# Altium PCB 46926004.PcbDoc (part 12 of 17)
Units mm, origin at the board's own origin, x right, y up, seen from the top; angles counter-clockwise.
Board outline 250 x 200 mm, 6 copper layers (Top Layer, INT1_GND, INT2_SIG, INT3_SIG, INT4_GND, Bottom Layer), stack 1.71 mm thick; 1450 components, 1293 nets, 5656 pads, 2307 vias.
Unrouted connection lines stored in the file: 2.
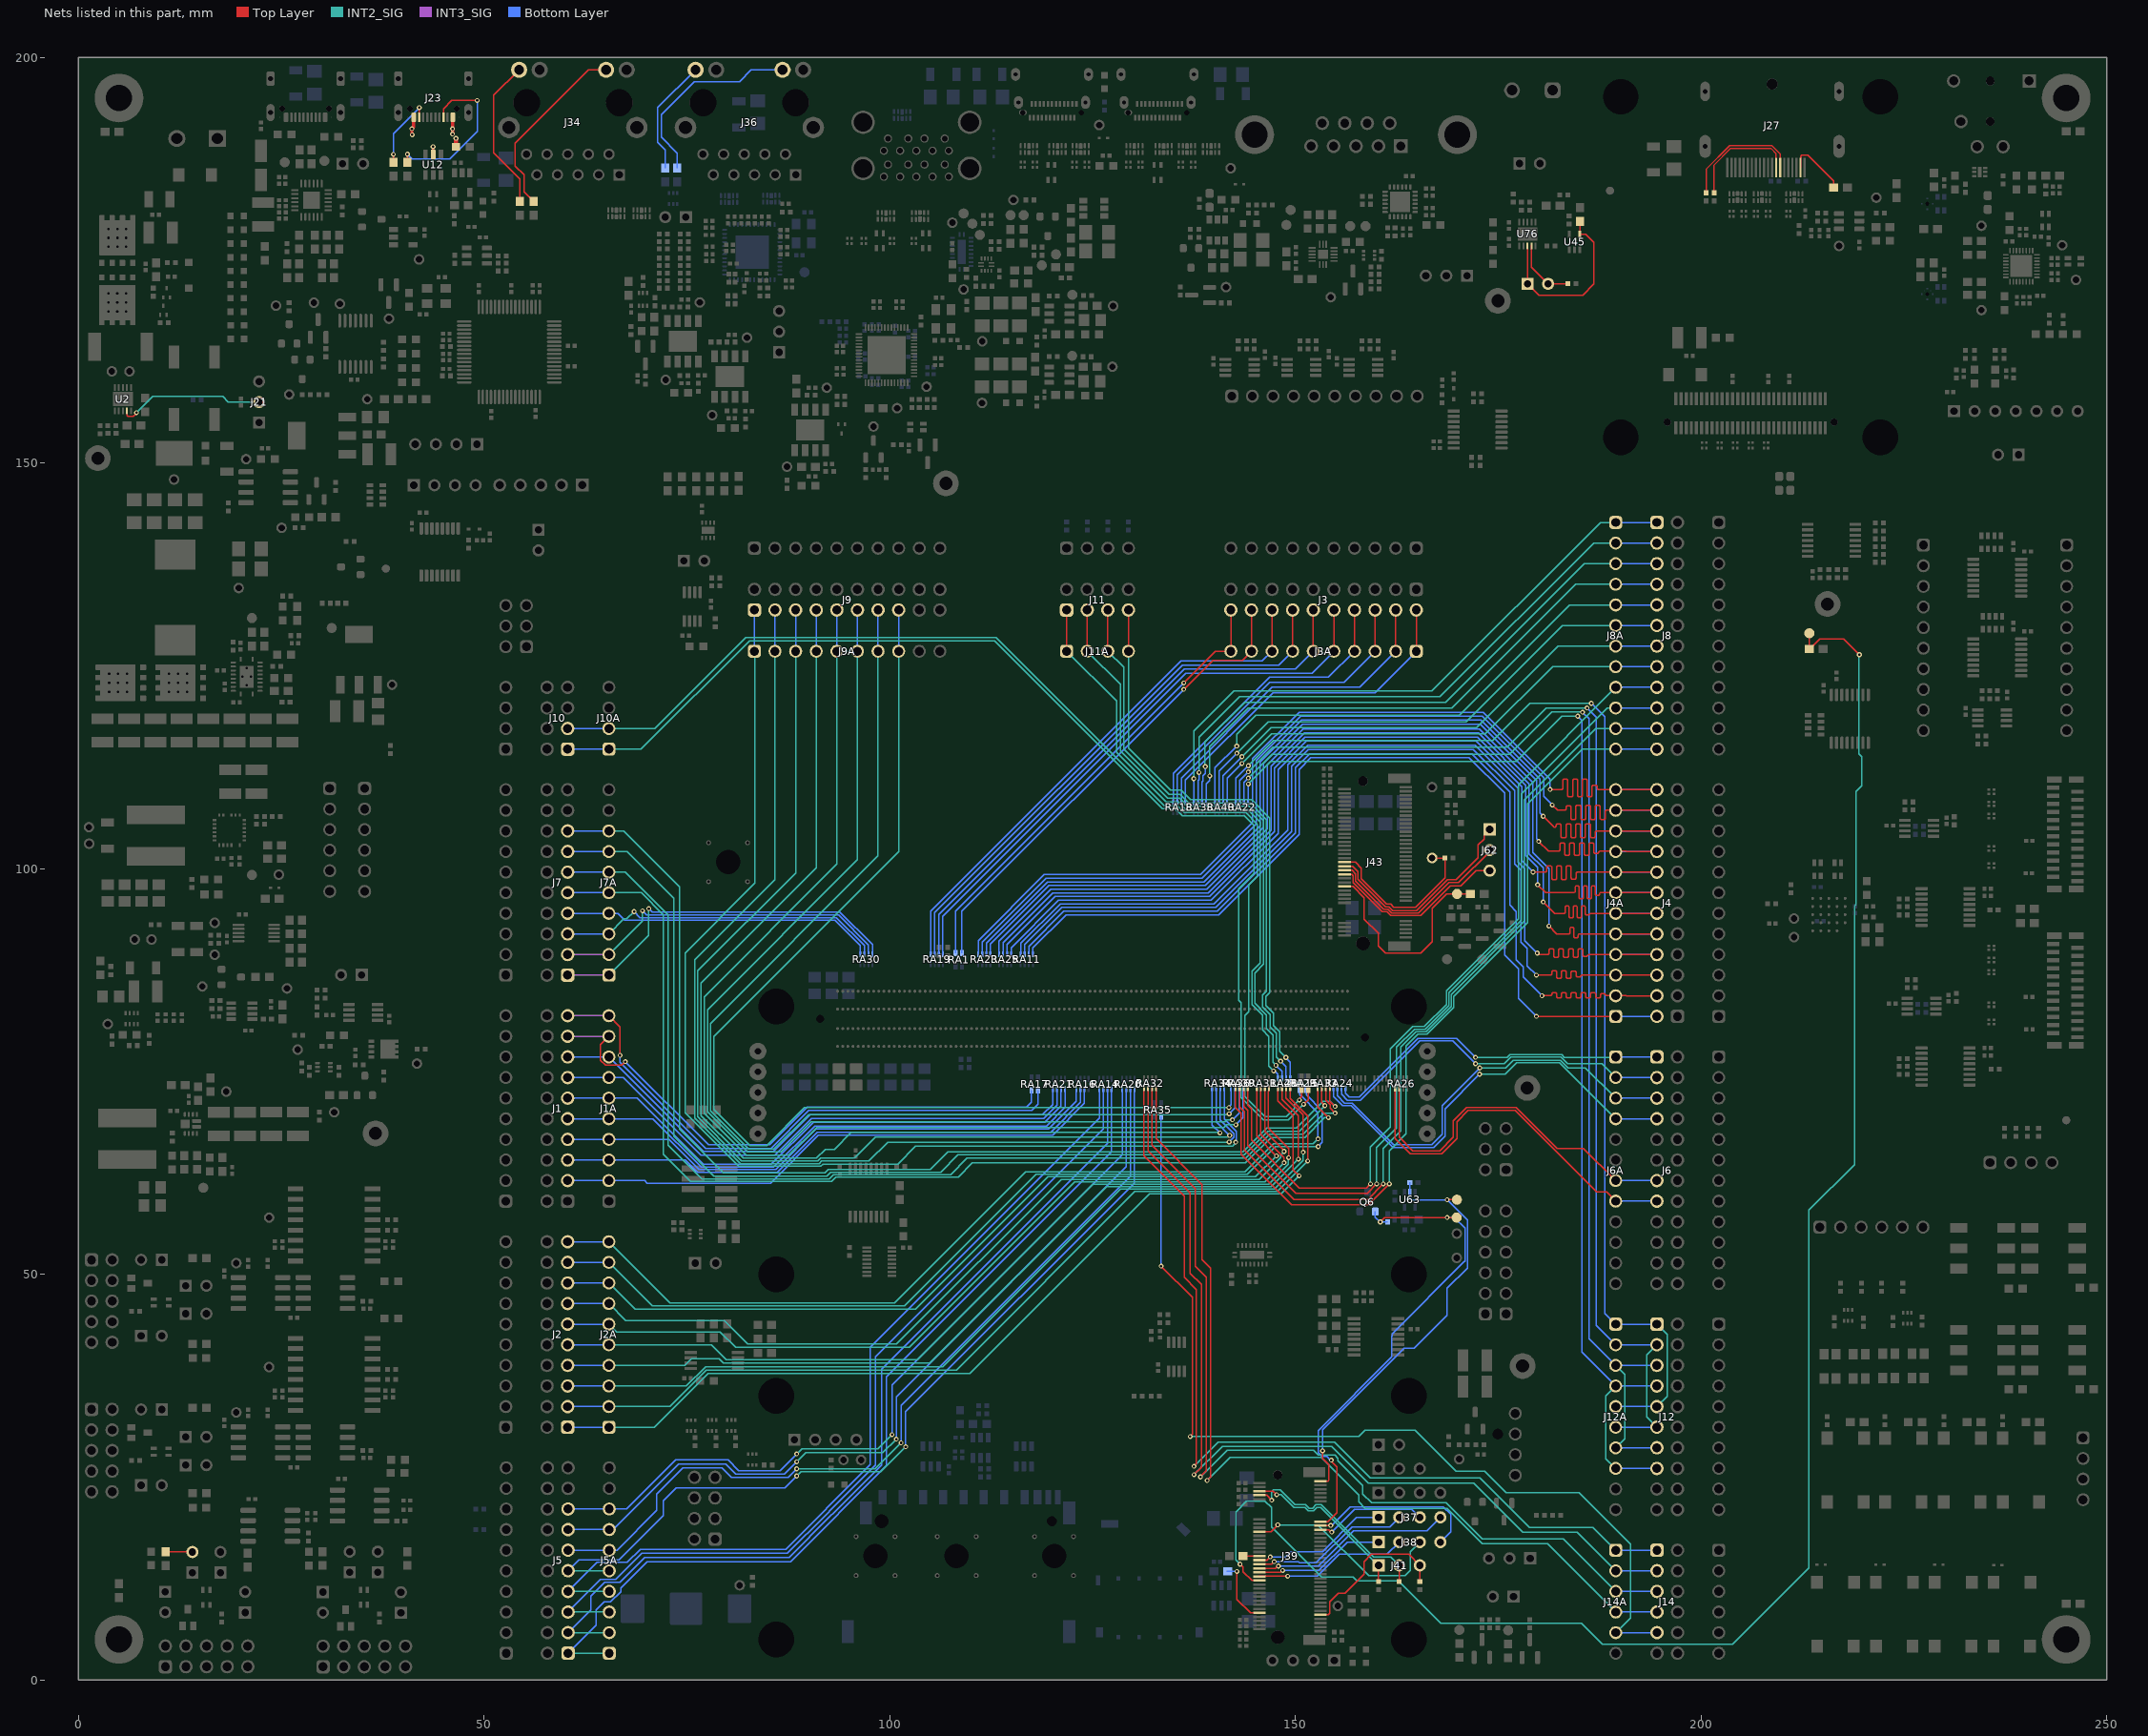
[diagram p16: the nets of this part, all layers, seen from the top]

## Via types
v1: diameter 0.6, hole 0.3, Top Layer to Bottom Layer, tented both sides, 2171 vias
v2: diameter 0.6, hole 0.3, Top Layer to Bottom Layer, 48 vias
v3: diameter 1, hole 0.5, Top Layer to Bottom Layer, tented both sides, 37 vias
v4: diameter 0.5, hole 0.2, Top Layer to Bottom Layer, tented both sides, 34 vias
v5: diameter 0.6, hole 0.3, Top Layer to Bottom Layer, tented bottom, 17 vias

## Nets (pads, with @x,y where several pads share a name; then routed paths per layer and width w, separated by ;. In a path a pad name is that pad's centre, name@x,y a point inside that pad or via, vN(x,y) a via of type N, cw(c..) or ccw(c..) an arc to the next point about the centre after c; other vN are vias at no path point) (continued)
NetJ1_3: J1.3 J1A.2 RA16.6 | length 69.7
  Bottom Layer w0.15: J1.3@60.3,61.56 69.78,61.56 70.09,61.25 85.285,61.25 91.214,67.179 120.106,67.179 123.996,71.069 RA16.6@123.996,72.872
NetJ1_5: J1.5 J1A.3 RA16.7 | length 69.1
  Bottom Layer w0.15: J1.5@60.3,64.1 J1A.3@65.38,64.1 74.8,64.1 76.316,62.584 86.117,62.584 91.067,67.534 119.836,67.534 123.496,71.194 RA16.7@123.496,72.872
NetJ1_7: J1.7 J1A.4 RA16.8 | length 69.3
  Bottom Layer w0.15: J1.7@60.3,66.64 J1A.4@65.38,66.64 72.817,66.64 76.523,62.934 85.952,62.934 90.916,67.899 119.567,67.899 122.996,71.328 RA16.8@122.996,72.872
NetJ1_9: J1.9 J1A.5 RA21.5 | length 69.1
  Bottom Layer w0.15: J1.9@60.3,69.18 64.05,69.18 J1A.5@65.38,69.18 70.82,69.18 76.766,63.234 85.692,63.234 90.752,68.295 119.302,68.295 121.61,70.602 RA21.5@121.61,72.87
NetJ1_11: J1.11 J1A.6 RA21.6 | length 69.3
  Bottom Layer w0.15: J1.11@60.3,71.72 64.05,71.72 J1A.6@65.38,71.72 68.885,71.72 77.056,63.549 85.397,63.549 90.574,68.725 119.119,68.725 121.11,70.716 RA21.6@121.11,72.87
NetJ1_13: J1.13 J1A.7 RA21.7 | length 68.9
  Bottom Layer w0.15: J1.13@60.3,74.26 J1A.7@65.38,74.26 67.14,74.26 76.717,64.683 85.87,64.683 90.38,69.193 118.957,69.193 120.61,70.846 RA21.7@120.61,72.87
NetJ1_15: J1.15 J1A.8 RA21.8 | length 68.9
  Bottom Layer w0.15: J1.15@60.3,76.8 J1A.8@65.3,76.8 ; J1A.8@65.38,76.8 77.037,65.143 85.678,65.143 90.189,69.654 118.831,69.654 120.11,70.934 RA21.8@120.11,72.87
NetJ1_17: J1.17 J1A.9 RA17.4 | length 69.9
  Top Layer w0.15: J1A.9@65.38,79.34 64.355,78.315 64.355,76.375 64.955,75.775 66.958,75.775 v1(67.4,76.217)
  INT3_SIG w0.15: J1.17@60.3,79.34 J1A.9@65.38,79.34
  Bottom Layer w0.15: v1(67.4,76.217) 77.664,65.953 85.195,65.953 89.842,70.6 116.856,70.6 117.476,71.22 RA17.4@117.476,72.67
NetJ1_19: J1.19 J1A.10 RA17.3 | length 71.2
  Top Layer w0.15: J1A.10@65.38,81.88 66.755,80.505 v1(66.755,77)
  INT3_SIG w0.15: J1.19@60.3,81.88 J1A.10@65.38,81.88
  Bottom Layer w0.15: v1(66.755,77) 66.755,76.119 77.334,65.54 85.347,65.54 90.007,70.2 117.482,70.2 118.276,70.993 RA17.3@118.276,72.67
NetJ2_1: J2.1 J2A.1 RA28.5 | length 114.9
  Top Layer w0.15: RA28.5@147.85,72.95 147.85,71.397 149.699,69.548 149.699,62.896 v1(150.444,62.152)
  INT2_SIG w0.15: J2A.1@65.38,31.16 70.96,31.16 77.6,37.8 109.9,37.8 132.017,59.917 148.209,59.917 v1(150.444,62.152)
  Bottom Layer w0.15: J2.1@60.3,31.16 J2A.1@65.38,31.16
NetJ2_3: J2.3 J2A.2 RA28.8 | length 113.6
  Top Layer w0.15: RA28.8@149.35,72.95 149.355,72.945 149.355,71.883 149.361,71.877 149.361,71.669 151.52,69.51 v1(151.52,63.97)
  INT2_SIG w0.15: J2A.2@65.38,33.7 72.893,33.7 77.407,38.214 108.214,38.214 130.217,60.217 147.766,60.217 v1(151.52,63.97)
  Bottom Layer w0.15: J2.3@60.3,33.7 J2A.2@65.38,33.7
NetJ2_5: J2.5 J2A.3 RA28.7 | length 111.9
  Top Layer w0.15: RA28.7@148.85,72.95 148.85,71.755 150.951,69.653 v1(150.951,65.052)
  INT2_SIG w0.15: J2A.3@65.38,36.24 74.94,36.24 77.3,38.6 106.5,38.6 128.417,60.517 147.418,60.517 150.951,64.05 v1(150.951,65.052)
  Bottom Layer w0.15: J2.5@60.3,36.24 J2A.3@65.38,36.24
NetJ2_7: J2.7 J2A.4 RA28.6 | length 110.6
  Top Layer w0.15: RA28.6@148.35,72.95 148.35,71.584 150.365,69.569 v1(150.365,64.207)
  INT2_SIG w0.15: J2A.4@65.38,38.78 74.751,38.78 75.576,39.605 78.969,39.605 79.524,39.05 104.95,39.05 126.717,60.817 146.975,60.817 v1(150.365,64.207)
  Bottom Layer w0.15: J2.7@60.3,38.78 J2A.4@65.38,38.78
NetJ2_9: J2.9 J2A.5 RA31.8 | length 110.1
  Top Layer w0.15: RA31.8@146.733,72.95 146.683,72.9 146.683,72.583 146.663,72.562 146.663,68.025 149.162,65.525 v1(149.162,64.369)
  INT2_SIG w0.15: J2A.5@65.28,41.32 J2A.5@65.38,41.32 78.004,41.32 79.824,39.5 103.4,39.5 125.017,61.117 146.704,61.117 149.14,63.553 149.14,64.347 v1(149.162,64.369)
  Bottom Layer w0.15: J2.9@60.3,41.32 J2A.5@65.38,41.32
NetJ2_11: J2.11 J2A.6 RA31.6 | length 109.3
  Top Layer w0.15: RA31.6@145.733,72.95 145.733,67.277 148.615,64.395 v1(148.615,63.771)
  INT2_SIG w0.15: J2A.6@65.38,43.86 66.355,42.885 79.109,42.885 80.994,41 102.4,41 122.817,61.417 146.261,61.417 v1(148.615,63.771)
  Bottom Layer w0.15: J2.11@60.3,43.86 J2A.6@65.38,43.86
NetJ2_13: J2.13 J2A.7 RA31.7 | length 109.2
  Top Layer w0.15: RA31.7@146.233,72.95 146.233,67.621 148.598,65.256 v1(148.598,65.155)
  INT2_SIG w0.15: J2A.7@65.38,46.4 67.48,44.3 79.6,44.3 82.5,41.4 100.824,41.4 121.141,61.717 145.527,61.717 148.193,64.383 148.193,64.711 148.598,65.117 v1(148.598,65.155)
  Bottom Layer w0.15: J2.13@60.3,46.4 J2A.7@65.38,46.4
NetJ2_15: J2.15 J2A.8 RA31.5 | length 105.9
  Top Layer w0.15: RA31.5@145.233,72.95 145.233,67.035 v1(147.668,64.6)
  INT2_SIG w0.15: J2A.8@65.38,48.94 68.62,45.7 103.2,45.7 119.517,62.017 145.085,62.017 v1(147.668,64.6)
  Bottom Layer w0.15: J2.15@60.3,48.94 J2A.8@65.38,48.94
NetJ2_17: J2.17 J2A.9 RA29.3 | length 110.9
  INT2_SIG w0.15: J2A.9@65.38,51.48 70.767,46.093 101.793,46.093 118.017,62.317 144.076,62.317 147.503,65.743 v1(152.801,65.743)
  Bottom Layer w0.15: J2.17@60.3,51.48 J2A.9@65.38,51.48 ; RA29.3@151.325,72.75 151.325,72.147 153.314,70.158 153.314,66.256 v1(152.801,65.743)
NetJ2_19: J2.19 J2A.10 RA29.4 | length 111
  INT2_SIG w0.15: J2A.10@65.38,54.02 72.9,46.5 100.6,46.5 116.717,62.617 143.8,62.617 147.283,66.1 152.193,66.1 v1(152.789,66.696)
  Bottom Layer w0.15: J2.19@60.3,54.02 J2A.10@65.38,54.02 ; RA29.4@150.525,72.75 150.557,72.718 150.557,72.125 150.675,72.007 150.695,72.007 152.789,69.913 v1(152.789,66.696)
NetJ3_2: J3.2 J3A.1 RA18.8 | length 42.8
  Top Layer w0.15: J3A.1@164.9,126.81 J3.2@164.9,131.89
  Bottom Layer w0.15: RA18.8@136.431,108.2 136.431,110.907 147.224,121.7 159.79,121.7 J3A.1@164.9,126.81
NetJ3_4: J3.4 J3A.2 RA18.7 | length 41
  Top Layer w0.15: J3A.2@162.36,126.81 J3.4@162.36,131.89
  Bottom Layer w0.15: RA18.7@135.931,108.2 135.931,111.182 147.148,122.4 157.95,122.4 J3A.2@162.36,126.81
NetJ3_6: J3.6 J3A.3 RA18.6 | length 39.2
  Top Layer w0.15: J3A.3@159.82,126.81 J3.6@159.82,131.89
  Bottom Layer w0.15: RA18.6@135.431,108.2 135.431,111.592 146.839,123 156.01,123 J3A.3@159.82,126.81
NetJ3_8: J3.8 J3A.4 RA18.5 | length 37.2
  Top Layer w0.15: J3A.4@157.28,126.81 J3.8@157.28,131.89
  Bottom Layer w0.15: RA18.5@134.931,108.2 134.931,111.723 146.808,123.6 154.07,123.6 J3A.4@157.28,126.81
NetJ3_10: J3.10 J3A.5 RA19.8 | length 71.5
  Top Layer w0.15: J3A.5@154.74,126.81 J3.10@154.74,131.89
  Bottom Layer w0.15: RA19.8@106.55,89.45 106.55,94.153 136.497,124.1 152.03,124.1 J3A.5@154.74,126.81
NetJ3_12: J3.12 J3A.6 RA19.7 | length 69.6
  Top Layer w0.15: J3A.6@152.2,126.81 J3.12@152.2,131.89
  Bottom Layer w0.15: RA19.7@106.05,89.45 106.05,94.36 136.29,124.6 149.99,124.6 J3A.6@152.2,126.81
NetJ3_14: J3.14 J3A.7 RA19.6 | length 67.7
  Top Layer w0.15: J3A.7@149.66,126.81 J3.14@149.66,131.89
  Bottom Layer w0.15: RA19.6@105.55,89.45 105.55,94.568 136.082,125.1 147.95,125.1 J3A.7@149.66,126.81
NetJ3_16: J3.16 J3A.8 RA19.5 | length 65.7
  Top Layer w0.15: J3A.8@147.12,126.81 J3.16@147.12,131.89
  Bottom Layer w0.15: RA19.5@105.05,89.45 105.05,94.775 135.875,125.6 145.91,125.6 J3A.8@147.12,126.81
NetJ3_18: J3.18 J3A.9 RA1.4 | length 59.2
  Top Layer w0.15: v1(136.24,122.114) 139.826,125.7 143.47,125.7 J3A.9@144.58,126.81 J3.18@144.58,131.89
  Bottom Layer w0.15: RA1.4@108.9,89.6 108.9,94.774 v1(136.24,122.114)
NetJ3_20: J3.20 J3A.10 RA1.3 | length 57.5
  Top Layer w0.15: v1(136.24,122.9) 140.15,126.81 J3A.10@142.04,126.81 J3.20@142.04,131.89
  Bottom Layer w0.15: RA1.3@108.1,89.6 108.1,94.76 v1(136.24,122.9)
NetJ4_2: J4.2 J4A.1 RA11.8 | length 119.1
  Top Layer w0.15: v1(179.7,81.8) 182.415,81.8 185.291,81.8 J4A.1@189.47,81.8
  Bottom Layer w0.15: RA11.8@117.634,89.45 117.634,90.228 121.726,94.32 140.553,94.32 150.45,104.218 150.45,112.25 151.881,113.681 171.404,113.681 175.771,109.313 175.771,89.387 177.478,87.68 177.478,84.022 v1(179.7,81.8) ; J4A.1@189.47,81.8 J4.2@194.55,81.8
NetJ4_4: J4.4 J4A.2 RA11.7 | length 122.8
  Top Layer w0.15: v1(180.4,84.344) 181.39,84.344 181.465,84.344 181.585,84.464 181.585,84.606 181.705,84.726 182.065,84.726 182.185,84.606 182.185,84.22 182.305,84.1 182.665,84.1 182.785,84.22 182.785,84.606 182.905,84.726 183.265,84.726 183.385,84.606 183.385,84.22 183.505,84.1 183.865,84.1 183.985,84.22 183.985,84.606 184.105,84.726 184.465,84.726 184.585,84.606 184.585,84.22 184.705,84.1 185.065,84.1 185.185,84.22 185.185,84.606 185.305,84.726 185.665,84.726 185.785,84.606 185.785,84.22 185.905,84.1 186.265,84.1 186.385,84.22 186.385,84.606 186.505,84.726 186.865,84.726 186.985,84.606 186.985,84.22 187.105,84.1 187.465,84.1 187.585,84.22 187.585,84.499 187.705,84.619 188.065,84.619 188.185,84.499 188.185,84.464 188.305,84.344 188.887,84.344 190.796,84.344 ; 190.8,84.34 J4.4@194.55,84.34
  Bottom Layer w0.15: RA11.7@117.134,89.45 117.134,90.435 121.469,94.77 140.366,94.77 150,104.404 150,112.436 151.745,114.181 171.733,114.181 176.435,109.479 176.435,95.524 177.218,94.741 177.218,94.018 177.2,94 177.2,88.765 178.061,87.904 178.061,86.683 v1(180.4,84.344)
NetJ4_6: J4.6 J4A.3 RA11.6 | length 121.3
  Top Layer w0.15: v1(179.7,86.88) 181.39,86.88 181.465,86.88 181.585,87 181.585,87.285 181.705,87.405 182.065,87.405 182.185,87.285 182.185,86.583 182.305,86.463 182.665,86.463 182.785,86.583 182.785,87.285 182.905,87.405 183.265,87.405 183.385,87.285 183.385,86.583 183.505,86.463 183.865,86.463 183.985,86.583 183.985,87.256 184.105,87.376 184.465,87.376 184.585,87.256 184.585,86.76 184.705,86.64 185.065,86.64 185.185,86.76 185.305,86.88 187.367,86.88 J4A.3@189.47,86.88 J4.6@194.55,86.88
  Bottom Layer w0.15: RA11.6@116.634,89.45 116.634,90.642 121.212,95.22 140.18,95.22 149.55,104.591 149.55,112.622 151.609,114.681 171.94,114.681 177,109.621 177,100.609 177.802,99.806 177.802,90.945 178.562,90.185 178.562,88.018 v1(179.7,86.88)
NetJ4_8: J4.8 J4A.4 RA11.5 | length 128.1
  Top Layer w0.15: v1(179.8,89.6) 179.922,89.6 180.102,89.42 181.05,89.42 181.125,89.42 181.245,89.54 181.245,90.03 181.365,90.15 181.725,90.15 181.845,90.03 181.845,89.183 181.965,89.063 182.325,89.063 182.445,89.183 182.445,90.03 182.565,90.15 182.925,90.15 183.045,90.03 183.045,89.183 183.165,89.063 183.525,89.063 183.645,89.183 183.645,90.03 183.765,90.15 184.125,90.15 184.245,90.03 184.245,89.183 184.365,89.063 184.725,89.063 184.845,89.183 184.845,90.027 184.965,90.147 185.325,90.147 185.445,90.027 185.445,89.3 185.565,89.18 185.925,89.18 186.045,89.3 186.165,89.42 187.783,89.42 J4A.4@189.47,89.42 J4.8@194.55,89.42
  Bottom Layer w0.15: RA11.5@116.134,89.45 116.168,89.483 116.168,90.829 121.009,95.67 139.977,95.67 149.083,104.777 149.083,112.809 151.5,115.225 172.137,115.225 177.45,109.912 177.45,100.795 178.252,99.992 178.252,91.131 179.784,89.6 v1(179.8,89.6) ; J4A.4@189.47,89.42 J4.8@194.55,89.42
NetJ4_10: J4.10 J4A.5 RA25.5 | length 125.1
  Top Layer w0.15: v1(181.247,92.931) 182.218,91.96 183.645,91.96 183.72,91.96 183.82,92.06 183.82,92.655 183.92,92.755 184.22,92.755 184.32,92.655 184.32,91.588 184.42,91.488 184.72,91.488 184.82,91.588 184.82,91.86 184.92,91.96 185.383,91.96 J4A.5@189.47,91.96 J4.10@194.55,91.96
  Bottom Layer w0.15: RA25.5@113.475,89.45 113.475,91.084 119.862,97.47 139.062,97.47 146.528,104.936 146.528,112.799 150.954,117.225 172.683,117.225 179.25,110.658 179.25,102.018 181.247,100.021 v1(181.247,92.931) ; J4A.5@189.47,91.96 J4.10@194.55,91.96
NetJ4_12: J4.12 J4A.6 RA25.6 | length 126.4
  Top Layer w0.15: v1(180.536,95.9) 181.936,94.5 183.069,94.5 183.144,94.5 183.244,94.6 183.244,95.327 183.344,95.427 183.644,95.427 183.744,95.327 183.744,94.057 183.844,93.957 184.144,93.957 184.244,94.057 184.244,95.327 184.344,95.427 184.644,95.427 184.744,95.327 184.744,94.057 184.844,93.957 185.144,93.957 185.244,94.057 185.244,95.293 185.344,95.393 185.644,95.393 185.744,95.293 185.744,94.4 185.844,94.3 186.144,94.3 186.244,94.4 186.344,94.5 186.989,94.5 J4A.6@189.47,94.5 J4.12@194.55,94.5
  Bottom Layer w0.15: RA25.6@113.975,89.45 113.975,90.887 120.108,97.02 139.249,97.02 146.978,104.749 146.978,112.612 151.09,116.725 172.546,116.725 178.8,110.471 178.8,101.832 180.536,100.096 v1(180.536,95.9) ; J4A.6@189.47,94.5 J4.12@194.55,94.5
NetJ4_14: J4.14 J4A.7 RA25.7 | length 123.5
  Top Layer w0.15: v1(179.848,98.022) 180.83,97.04 184.29,97.04 184.365,97.04 184.465,97.14 184.465,97.762 184.565,97.862 184.865,97.862 184.965,97.762 184.965,96.405 185.065,96.305 185.365,96.305 185.465,96.405 185.465,97.762 185.565,97.862 185.865,97.862 185.965,97.762 185.965,96.405 186.065,96.305 186.365,96.305 186.465,96.405 186.465,97.762 186.565,97.862 186.865,97.862 186.965,97.762 186.965,96.817 187.065,96.717 187.365,96.717 187.465,96.817 187.465,96.94 187.565,97.04 187.847,97.04 J4A.7@189.47,97.04 J4.14@194.55,97.04
  Bottom Layer w0.15: RA25.7@114.475,89.45 114.475,90.67 120.376,96.57 139.435,96.57 147.428,104.563 147.428,112.426 151.202,116.2 172.435,116.2 178.35,110.285 178.35,101.645 179.848,100.148 v1(179.848,98.022) ; J4A.7@189.47,97.04 J4.14@194.55,97.04
NetJ4_16: J4.16 J4A.8 RA25.8 | length 121.7
  Top Layer w0.15: v1(179.291,99.59) 179.301,99.58 180.787,99.58 180.862,99.58 180.982,99.7 180.982,100.236 181.102,100.356 181.462,100.356 181.582,100.236 181.582,98.779 181.702,98.659 182.062,98.659 182.182,98.779 182.182,100.236 182.302,100.356 182.662,100.356 182.782,100.236 182.782,98.779 182.902,98.659 183.262,98.659 183.382,98.779 183.382,100.236 183.502,100.356 183.862,100.356 183.982,100.236 183.982,98.854 184.102,98.734 184.462,98.734 184.582,98.854 184.582,99.46 184.702,99.58 186.009,99.58 J4A.8@189.47,99.58 190.78,99.58 ; 190.79,99.59 190.78,99.58 ; J4.16@194.55,99.58 190.78,99.58
  Bottom Layer w0.15: RA25.8@114.975,89.45 114.975,90.273 120.823,96.12 139.622,96.12 147.878,104.377 147.878,112.24 151.363,115.725 172.274,115.725 177.9,110.099 177.9,100.981 v1(179.291,99.59) ; J4A.8@189.47,99.58 J4.16@194.55,99.58
NetJ4_18: J4.18 J4A.9 RA23.8 | length 125.4
  Top Layer w0.15: v1(179.981,103.367) 181.197,102.15 182.4,102.15 182.475,102.15 182.595,102.27 182.595,103.026 182.715,103.146 183.075,103.146 183.195,103.026 183.195,101.739 183.315,101.619 183.675,101.619 183.795,101.739 183.795,103.026 183.915,103.146 184.275,103.146 184.395,103.026 184.395,101.739 184.515,101.619 184.875,101.619 184.995,101.739 184.995,103.026 185.115,103.146 185.475,103.146 185.595,103.026 185.595,101.739 185.715,101.619 186.075,101.619 186.195,101.739 186.195,103.026 186.315,103.146 186.675,103.146 186.795,103.026 186.795,102.002 186.915,101.882 187.275,101.882 187.395,102.002 187.395,102.03 187.515,102.15 188.246,102.15 189.47,102.15 190.77,102.15 190.8,102.12 J4.18@194.55,102.12
  Bottom Layer w0.15: RA23.8@112.4,89.45 112.4,90.703 119.617,97.92 138.876,97.92 146.078,105.122 146.078,112.985 150.868,117.775 172.769,117.775 179.7,110.844 179.7,103.68 179.981,103.399 v1(179.981,103.367) ; J4A.9@189.47,102.12 J4.18@194.55,102.12
NetJ4_20: J4.20 J4A.10 RA23.7 | length 125.1
  Top Layer w0.15: v1(180.536,106.46) 181.783,105.213 181.858,105.138 182.027,105.138 182.147,105.258 182.147,105.418 182.267,105.538 182.627,105.538 182.747,105.418 182.747,103.932 182.867,103.812 183.227,103.812 183.347,103.932 183.347,105.418 183.467,105.538 183.827,105.538 183.947,105.418 183.947,103.932 184.067,103.812 184.427,103.812 184.547,103.932 184.547,105.418 184.667,105.538 185.027,105.538 185.147,105.418 185.147,103.932 185.267,103.812 185.627,103.812 185.747,103.932 185.747,105.418 185.867,105.538 186.227,105.538 186.347,105.418 186.347,103.932 186.467,103.812 186.827,103.812 186.947,103.932 186.947,104.54 187.067,104.66 188.62,104.66 J4A.10@189.47,104.66 J4.20@194.55,104.66
  Bottom Layer w0.15: RA23.7@111.9,89.45 111.9,90.84 119.431,98.37 138.69,98.37 145.628,105.309 145.628,113.172 150.781,118.325 172.856,118.325 180.15,111.031 180.15,106.846 v1(180.536,106.46) ; J4A.10@189.47,104.66 J4.20@194.55,104.66
NetJ4_22: J4.22 J4A.11 RA23.6 | length 125
  Top Layer w0.15: v1(181.652,107.862) 181.674,107.84 182.314,107.2 183.251,107.2 183.371,107.32 183.371,107.617 183.491,107.737 183.851,107.737 183.971,107.617 183.971,106.156 184.091,106.036 184.451,106.036 184.571,106.156 184.571,107.713 184.691,107.833 185.051,107.833 185.171,107.713 185.171,106.156 185.291,106.036 185.651,106.036 185.771,106.156 185.771,107.713 185.891,107.833 186.251,107.833 186.371,107.713 186.371,106.156 186.491,106.036 186.851,106.036 186.971,106.156 186.971,107.713 187.091,107.833 187.451,107.833 187.571,107.713 187.571,106.156 187.691,106.036 188.051,106.036 188.171,106.156 188.171,107.08 188.291,107.2 188.366,107.2 J4A.11@189.47,107.2 J4.22@194.55,107.2
  Bottom Layer w0.15: RA23.6@111.4,89.45 111.4,90.976 119.244,98.82 138.503,98.82 145.178,105.495 145.178,113.358 150.62,118.8 173.017,118.8 180.6,111.217 180.6,108.914 v1(181.652,107.862) ; J4A.11@189.47,107.2 J4.22@194.55,107.2
NetJ4_24: J4.24 J4A.12 RA23.5 | length 124.3
  Top Layer w0.15: v1(181.387,109.774) 181.421,109.74 182.774,109.74 182.849,109.74 182.969,109.86 182.969,110.924 183.089,111.044 183.449,111.044 183.569,110.924 183.569,109.014 183.689,108.894 184.049,108.894 184.169,109.014 184.169,110.924 184.289,111.044 184.649,111.044 184.769,110.924 184.769,109.014 184.889,108.894 185.249,108.894 185.369,109.014 185.369,110.924 185.489,111.044 185.849,111.044 185.969,110.924 185.969,109.014 186.089,108.894 186.449,108.894 186.569,109.014 186.569,110.174 186.689,110.294 187.049,110.294 187.169,110.174 187.169,109.86 187.289,109.74 189.451,109.74 J4A.12@189.47,109.74 J4.24@194.55,109.74
  Bottom Layer w0.15: RA23.5@110.9,89.45 110.9,91.112 119.058,99.27 138.317,99.27 144.728,105.681 144.728,113.544 150.483,119.3 173.153,119.3 181.387,111.067 v1(181.387,109.774) ; J4A.12@189.47,109.74 J4.24@194.55,109.74
NetJ5_1: J5.1 J5A.1 RA14.5 | length 113.2
  INT2_SIG w0.15: J5.1@60.35,3.3 J5A.1@65.43,3.3
  Bottom Layer w0.15: J5.1@60.35,3.3 63.801,6.751 63.801,8.623 64.801,9.623 65.582,9.623 66.85,10.89 66.85,11.348 70.102,14.6 87.786,14.6 99.6,26.414 99.6,37.346 127.325,65.071 RA14.5@127.325,72.872
NetJ5_3: J5.3 J5A.2 RA14.6 | length 111.2
  INT2_SIG w0.15: J5.3@60.35,5.84 J5A.2@65.43,5.84
  Bottom Layer w0.15: J5.3@60.35,5.84 63.148,8.638 63.148,10.338 64.845,12.035 66.727,12.035 69.793,15.1 87.579,15.1 92.684,20.205 93.115,20.636 98.975,26.496 98.975,38.335 126.825,66.185 RA14.6@126.825,72.872
NetJ5_5: J5.5 J5A.3 RA14.7 | length 108.5
  INT2_SIG w0.15: J5.5@60.35,8.38 J5A.3@65.43,8.38
  Bottom Layer w0.15: J5.5@60.35,8.38 64.344,12.374 66.235,12.374 69.461,15.6 87.372,15.6 92.175,20.403 92.917,21.145 98.25,26.478 98.25,39.85 126.325,67.925 RA14.7@126.325,72.872
NetJ5_7: J5.7 J5A.4 RA14.8 | length 106.8
  INT2_SIG w0.15: J5.7@60.35,10.92 J5A.4@65.43,10.92
  Bottom Layer w0.15: J5.7@60.35,10.92 63.93,14.5 67.654,14.5 69.254,16.1 87.165,16.1 91.765,20.7 92.62,21.555 97.6,26.535 97.6,41.029 125.825,69.254 RA14.8@125.825,72.872
NetJ5_9: J5.9 J5A.5 RA20.5 | length 109.9
  INT2_SIG w0.15: J5.9@60.35,13.46 J5A.5@65.43,13.46 ; v1(88.537,25.15) 89.057,25.67 98.894,25.67 v1(101.966,28.742)
  Bottom Layer w0.15: J5.9@60.35,13.46 61.69,14.8 66.616,14.8 72.096,20.28 72.096,22.096 73.679,23.679 87.079,23.679 88.537,25.137 v1(88.537,25.15) ; v1(101.966,28.742) 101.966,33.066 130.15,61.25 RA20.5@130.15,72.872
NetJ5_11: J5.11 J5A.6 RA20.6 | length 104
  INT2_SIG w0.15: v1(88.537,26.035) 98.201,26.035 v1(101.399,29.233)
  Bottom Layer w0.15: J5.11@60.35,16 64.1,16 66.367,16 71.295,20.928 71.295,22.932 74.523,26.16 79.3,26.16 80.475,24.985 87.487,24.985 v1(88.537,26.035) ; v1(101.399,29.233) 101.399,33.87 129.65,62.121 RA20.6@129.65,72.872
NetJ5_13: J5.13 J5A.7 RA20.7 | length 101
  INT2_SIG w0.15: v1(88.537,26.904) 89.653,28.02 99.135,28.02 v1(100.8,29.685)
  Bottom Layer w0.15: J5.13@60.35,18.54 64.1,18.54 65.94,18.54 74,26.6 79.8,26.6 81.04,25.36 86.993,25.36 v1(88.537,26.904) ; v1(100.8,29.685) 100.8,34.914 129.15,63.263 RA20.7@129.15,72.872
NetJ5_15: J5.15 J5A.8 RA20.8 | length 99.2
  INT2_SIG w0.15: v1(88.537,27.875) 89.162,28.5 98.519,28.5 v1(100.269,30.25)
  Bottom Layer w0.15: J5.15@60.35,21.08 64.1,21.08 67.58,21.08 73.633,27.133 80.075,27.133 81.398,25.81 86.472,25.81 v1(88.537,27.875) ; v1(100.269,30.25) 100.269,36.346 128.65,64.726 RA20.8@128.65,72.872
NetJ6_1: J6.1 J6A.1 RA24.5 | length 43.5
  INT2_SIG w0.15: v1(172.19,76.758) 176.099,76.758 176.441,77.1 182.823,77.1 183.165,76.758 189.428,76.758 J6A.1@189.47,76.8
  Bottom Layer w0.15: RA24.5@156.175,72.978 156.175,72.319 156.617,71.877 157.898,71.877 165.096,79.075 169.872,79.075 v1(172.19,76.758) ; J6A.1@189.47,76.8 J6.1@194.55,76.8
NetJ6_3: J6.3 J6A.2 RA24.6 | length 45.5
  INT2_SIG w0.15: v1(172.196,75.975) 175.74,75.975 176.565,76.8 182.699,76.8 183.524,75.975 187.755,75.975 J6A.2@189.47,74.26
  Bottom Layer w0.15: RA24.6@155.675,72.978 155.675,72.194 156.4,71.469 158.019,71.469 165.325,78.775 169.396,78.775 v1(172.196,75.975) ; J6A.2@189.47,74.26 J6.3@194.55,74.26
NetJ6_5: J6.5 J6A.3 RA24.7 | length 51.1
  INT2_SIG w0.15: v1(172.725,75.443) 175.919,75.443 176.872,76.396 182.678,76.396 183.631,75.443 185.747,75.443 J6A.3@189.47,71.72
  Bottom Layer w0.15: RA24.7@155.175,72.978 155.175,72.013 156.079,71.109 156.991,71.109 162.102,65.998 166.821,65.998 168.069,67.246 168.069,70.787 v1(172.725,75.443) ; J6A.3@189.47,71.72 J6.5@194.55,71.72
NetJ6_7: J6.7 J6A.4 RA24.8 | length 52.7
  INT2_SIG w0.15: v1(172.704,74.679) 175.825,74.679 177.241,76.096 182.554,76.096 J6A.4@189.47,69.18
  Bottom Layer w0.15: RA24.8@154.675,72.978 154.675,71.934 155.8,70.809 156.867,70.809 162.056,65.619 167.024,65.619 168.435,67.03 168.435,70.41 v1(172.704,74.679) ; J6A.4@189.47,69.18 J6.7@194.55,69.18
NetJ6_13: J6.13 J6A.7 RA26.6 | length 45.6
  Top Layer w0.15: RA26.6@162.785,72.928 162.785,66.92 164.466,65.239 167.776,65.239 169.471,66.934 169.471,68.936 171.111,70.575 177.225,70.575 182.279,65.521 185.509,65.521 J6A.7@189.47,61.56
  Bottom Layer w0.15: J6A.7@189.47,61.56 J6.13@194.55,61.56
NetJ6_15: J6.15 J6A.8 RA26.5 | length 47.3
  Top Layer w0.15: RA26.5@162.285,72.928 162.285,66.725 164.171,64.839 168.011,64.839 169.9,66.728 169.9,68.8 171.297,70.197 177.067,70.197 187.115,60.148 188.342,60.148 J6A.8@189.47,59.02
  Bottom Layer w0.15: J6A.8@189.47,59.02 J6.15@194.55,59.02
NetJ7_1: J7.1 J7A.1 RA30.8 | length 45.8
  INT3_SIG w0.15: J7.1@60.3,86.88 J7A.1@65.38,86.88
  INT2_SIG w0.15: J7A.1@65.38,86.88 70.3,91.8 v1(70.3,95.083)
  Bottom Layer w0.15: v1@70.362,95.026 70.713,94.675 93.83,94.675 97.875,90.63 RA30.8@97.875,89.45
NetJ7_3: J7.3 J7A.2 RA30.7 | length 42.9
  INT3_SIG w0.15: J7.3@60.3,89.42 J7A.2@65.38,89.42
  INT2_SIG w0.15: J7A.2@65.38,89.42 69.518,93.558 v1(69.518,94.804)
  Bottom Layer w0.15: v1(69.518,94.804) 70.022,94.3 93.7,94.3 97.375,90.625 RA30.7@97.375,89.45
NetJ7_5: J7.5 J7A.3 RA30.6 | length 40.5
  INT2_SIG w0.15: J7A.3@65.38,91.96 67.235,93.815 67.597,93.815 v1(68.5,94.718)
  Bottom Layer w0.15: J7.5@60.3,91.96 J7A.3@65.38,91.96 ; v1(68.5,94.718) 69.243,93.975 93.44,93.975 96.875,90.54 RA30.6@96.875,89.45
NetJ7_7: J7.7 J7A.4 RA30.5 | length 38.8
  Bottom Layer w0.15: J7.7@60.3,94.5 64.05,94.5 66.5,94.5 67.325,93.675 93.26,93.675 96.375,90.56 RA30.5@96.375,89.45
NetJ7_9: J7.9 J7A.5 RA33.5 | length 133.2
  Top Layer w0.15: RA33.5@152.747,72.948 152.747,70.781 152.741,70.775 152.741,70.651 v1(154.071,69.322)
  INT2_SIG w0.15: J7A.5@65.38,97.04 69.375,97.04 72.1,94.315 72.1,64.81 75.435,61.475 92.85,61.475 93.375,62 108.468,62 110.193,63.725 143.835,63.725 146.997,66.887 151.156,66.887 153.591,69.322 v1(154.071,69.322)
  Bottom Layer w0.15: J7.9@60.3,97.04 J7A.5@65.38,97.04
NetJ7_11: J7.11 J7A.6 RA33.7 | length 133.8
  Top Layer w0.15: RA33.7@153.747,72.948 153.747,71.417 154.272,70.892 154.272,70.497 v1(154.9,69.869)
  INT2_SIG w0.15: J7A.6@65.38,99.58 67.42,99.58 72.7,94.3 72.7,65.9 76.825,61.775 92.514,61.775 93.039,62.3 107.5,62.3 109.528,64.328 143.872,64.328 146.838,67.293 150.953,67.293 153.529,69.869 v1(154.9,69.869)
  Bottom Layer w0.15: J7.11@60.3,99.58 J7A.6@65.38,99.58
NetJ7_13: J7.13 J7A.7 RA33.6 | length 133
  Top Layer w0.15: RA33.6@153.247,72.948 153.24,72.941 153.24,71.182 v1(153.622,70.8)
  INT2_SIG w0.15: J7A.7@65.38,102.12 67.626,102.12 73.4,96.346 73.4,67.026 78.301,62.126 92.226,62.126 92.7,62.6 106.3,62.6 108.425,64.725 143.704,64.725 146.616,67.637 150.459,67.637 v1(153.622,70.8)
  Bottom Layer w0.15: J7.13@60.3,102.12 J7A.7@65.38,102.12
NetJ7_15: J7.15 J7A.8 RA33.8 | length 136
  Top Layer w0.15: RA33.8@154.247,72.948 154.247,71.353 v1(154.9,70.7)
  INT2_SIG w0.15: J7A.8@65.38,104.66 67.195,104.66 74.1,97.755 74.1,67.902 79.502,62.5 92,62.5 92.4,62.9 104.975,62.9 107.181,65.106 143.519,65.106 146.448,68.036 150.094,68.036 153.384,71.325 154.275,71.325 v1(154.9,70.7)
  Bottom Layer w0.15: J7.15@60.3,104.66 J7A.8@65.38,104.66
NetJ8_1: J8.1 J8A.1 RA38.5 | length 76.5
  INT2_SIG w0.15: v1(137.472,111.109) 137.472,116.97 142.402,121.9 166.808,121.9 187.588,142.68 J8A.1@189.47,142.68
  Bottom Layer w0.15: v1(137.472,111.109) 137.481,111.1 137.481,108.209 RA38.5@137.49,108.2 ; J8A.1@189.47,142.68 J8.1@194.55,142.68
NetJ8_3: J8.3 J8A.2 RA38.6 | length 74.4
  INT2_SIG w0.15: v1(138.115,111.849) 138.115,116.192 143.124,121.2 167.828,121.2 186.768,140.14 J8A.2@189.47,140.14
  Bottom Layer w0.15: RA38.6@137.99,108.2 137.99,110.854 138.115,110.979 v1(138.115,111.849) ; J8A.2@189.47,140.14 J8.3@194.55,140.14
NetJ8_5: J8.5 J8A.3 RA38.7 | length 72.4
  INT2_SIG w0.15: v1(138.9,112.584) 138.865,112.618 138.865,115.613 143.753,120.5 168.5,120.5 185.6,137.6 J8A.3@189.47,137.6
  Bottom Layer w0.15: RA38.7@138.49,108.2 138.49,110.676 138.615,110.801 138.615,111.472 138.9,111.757 v1(138.9,112.584) ; J8A.3@189.47,137.6 J8.5@194.55,137.6
NetJ8_7: J8.7 J8A.4 RA38.8 | length 70.4
  INT2_SIG w0.15: v1(139.434,111.439) 139.434,115.034 144.2,119.8 169.3,119.8 184.56,135.06 J8A.4@189.47,135.06
  Bottom Layer w0.15: RA38.8@138.99,108.2 138.99,110.453 139.434,110.897 v1(139.434,111.439) ; J8A.4@189.47,135.06 J8.7@194.55,135.06
NetJ8_9: J8.9 J8A.5 RA40.5 | length 67.9
  INT2_SIG w0.15: v1(142.775,115.124) 142.775,116.551 145.124,118.9 170.192,118.9 183.812,132.52 J8A.5@189.47,132.52
  Bottom Layer w0.15: RA40.5@140.08,108.2 140.08,112.429 v1(142.775,115.124) ; J8A.5@189.47,132.52 J8.9@194.55,132.52
NetJ8_11: J8.11 J8A.6 RA40.6 | length 65.2
  INT2_SIG w0.15: v1(142.787,114.236) 146.656,118.105 171.005,118.105 182.88,129.98 J8A.6@189.47,129.98
  Bottom Layer w0.15: RA40.6@140.58,108.2 140.58,112.029 v1(142.787,114.236) ; J8A.6@189.47,129.98 J8.11@194.55,129.98
NetJ8_13: J8.13 J8A.7 RA40.7 | length 63.4
  INT2_SIG w0.15: v1(143.4,113.804) 146.996,117.4 172.328,117.4 182.368,127.44 J8A.7@189.47,127.44
  Bottom Layer w0.15: RA40.7@141.08,108.2 141.08,111.484 v1(143.4,113.804) ; J8A.7@189.47,127.44 J8.13@194.55,127.44
NetJ8_15: J8.15 J8A.8 RA40.8 | length 61.6
  INT2_SIG w0.15: v1(143.4,112.961) 147.039,116.6 173.405,116.6 181.705,124.9 J8A.8@189.47,124.9
  Bottom Layer w0.15: RA40.8@141.58,108.2 141.58,111.141 v1(143.4,112.961) ; J8A.8@189.47,124.9 J8.15@194.55,124.9
NetJ8_17: J8.17 J8A.9 RA39.8 | length 103.6
  Top Layer w0.15: RA39.8@144.125,72.95 144.125,70.858 144.581,70.402 144.581,66.548 150.494,60.635 158.737,60.635 v1(159.251,61.149)
  INT2_SIG w0.15: v1(159.251,61.149) 159.251,65.666 161.719,68.133 161.719,77.805 164.439,80.525 165.847,80.525 168.6,83.278 168.6,84.941 177.478,93.82 177.478,110.368 J8A.9@189.47,122.36
  Bottom Layer w0.15: J8A.9@189.47,122.36 J8.17@194.55,122.36
NetJ8_19: J8.19 J8A.10 RA39.7 | length 103.4
  Top Layer w0.15: RA39.7@143.625,72.95 143.625,70.7 144.131,70.194 144.131,65.945 150.077,60 158.868,60 v1(160.017,61.149)
  INT2_SIG w0.15: v1(160.017,61.149) 160.017,65.626 162.45,68.059 162.45,78.006 164.669,80.225 165.971,80.225 168.9,83.154 168.9,84.711 177.853,93.664 177.853,109.228 188.445,119.82 J8A.10@189.47,119.82
  Bottom Layer w0.15: J8A.10@189.47,119.82 J8.19@194.55,119.82
NetJ8_21: J8.21 J8A.11 RA39.6 | length 103.5
  Top Layer w0.15: RA39.6@143.125,72.95 143.125,70.632 143.705,70.053 143.705,65.354 149.821,59.238 158.917,59.238 v1(160.828,61.149)
  INT2_SIG w0.15: v1(160.828,61.149) 160.828,65.508 163,67.679 163,78.046 164.879,79.925 166.096,79.925 169.2,83.029 169.2,84.501 178.214,93.515 178.214,108.471 187.023,117.28 J8A.11@189.47,117.28
  Bottom Layer w0.15: J8A.11@189.47,117.28 J8.21@194.55,117.28
NetJ8_23: J8.23 J8A.12 RA39.5 | length 103.6
  Top Layer w0.15: RA39.5@142.625,72.95 142.625,70.556 143.298,69.883 143.298,64.812 149.559,58.552 158.981,58.552 v1(161.578,61.149)
  INT2_SIG w0.15: v1(161.578,61.149) 161.578,65.239 163.65,67.31 163.65,78.15 165.125,79.625 166.22,79.625 169.5,82.905 169.5,84.255 178.6,93.355 178.6,107.972 185.368,114.74 J8A.12@189.47,114.74
  Bottom Layer w0.15: J8A.12@189.47,114.74 J8.23@194.55,114.74
NetJ9_1: J9.1 J9A.1 RA34.5 | length 144.7
  INT2_SIG w0.15: 81.034,63.691 74.8,69.924 74.8,89.62 83.4,98.22 83.4,126.73 J9A.1@83.32,126.81 ; 81.036,63.689 81.398,63.326 91.476,63.326 91.75,63.6 100.996,63.6 103.198,65.802 142.28,65.802 142.386,65.908 142.386,65.935 142.63,66.179 v1(142.63,66.3)
  Bottom Layer w0.15: J9A.1@83.32,126.81 J9.1@83.32,131.89 ; RA34.5@141.225,72.95 141.225,69.133 142.721,67.637 142.721,66.784 142.716,66.779 142.716,66.387 v1(142.63,66.3)
NetJ9_3: J9.3 J9A.2 RA34.6 | length 143.6
  INT2_SIG w0.15: 81.133,64.102 75.961,69.274 75.961,88.774 85.86,98.673 J9A.2@85.86,126.81 ; 81.135,64.1 81.584,63.651 91.276,63.651 91.586,63.961 91.885,63.961 97.403,63.961 99.742,66.3 141.801,66.3 v1(141.828,66.327)
  Bottom Layer w0.15: J9A.2@85.86,126.81 J9.3@85.86,131.89 ; RA34.6@140.725,72.95 140.725,69.05 142.421,67.354 142.421,66.908 141.839,66.327 v1(141.828,66.327)
NetJ9_5: J9.5 J9A.3 RA34.7 | length 143.1
  INT2_SIG w0.15: J9A.3@88.4,126.81 88.4,99.493 76.328,87.42 76.328,69.426 81.333,64.421 81.753,64.001 91.126,64.001 91.453,64.328 92.05,64.328 95.67,64.328 98.242,66.9 141.658,66.9 141.884,67.125 v1(141.896,67.125)
  Bottom Layer w0.15: J9A.3@88.4,126.81 J9.5@88.4,131.89 ; RA34.7@140.225,72.95 140.225,68.796 v1(141.896,67.125)
NetJ9_7: J9.7 J9A.4 RA34.8 | length 141.6
  INT2_SIG w0.15: 81.414,64.902 76.725,69.59 76.725,85.925 90.94,100.14 J9A.4@90.94,126.81 ; 81.416,64.9 81.988,64.328 90.976,64.328 92.041,65.394 93.16,65.394 95.266,67.5 140.621,67.5 v1(140.696,67.425)
  Bottom Layer w0.15: J9A.4@90.94,126.81 J9.7@90.94,131.89 ; RA34.8@139.725,72.95 139.725,68.396 v1(140.696,67.425)
NetJ9_9: J9.9 J9A.5 RA36.5 | length 143
  INT2_SIG w0.15: J9A.5@93.48,126.81 93.5,126.79 93.5,100.56 77.125,84.185 77.125,69.838 82.297,64.666 87.566,64.666 90.982,68.082 141.177,68.082 141.523,68.429 v1(142.672,68.429)
  Bottom Layer w0.15: J9A.5@93.48,126.81 J9.9@93.48,131.89 ; v1(142.672,68.429) 142.672,68.443 143.55,69.322 RA36.5@143.55,72.95
NetJ9_11: J9.11 J9A.6 RA36.6 | length 142.2
  INT2_SIG w0.15: J9A.6@96.02,126.81 96.02,101.121 77.536,82.636 77.536,70.008 82.467,65.076 86.576,65.076 90.33,68.83 141.32,68.83 141.54,69.05 v1(142.223,69.05)
  Bottom Layer w0.15: J9A.6@96.02,126.81 J9.11@96.02,131.89 ; v1(142.223,69.05) 143.05,69.876 RA36.6@143.05,72.95
NetJ9_13: J9.13 J9A.7 RA36.7 | length 141.4
  INT2_SIG w0.15: J9A.7@98.56,126.81 98.56,101.56 77.909,80.909 77.909,70.162 82.621,65.449 85.749,65.449 90,69.7 141.738,69.7 v1(141.828,69.79)
  Bottom Layer w0.15: J9A.7@98.56,126.81 J9.13@98.56,131.89 ; v1(141.828,69.79) 142.55,70.512 RA36.7@142.55,72.95
NetJ9_15: J9.15 J9A.8 RA36.8 | length 140.8
  INT2_SIG w0.15: J9A.8@101.1,126.81 101.1,102.1 78.325,79.325 78.325,70.335 82.794,65.866 84.816,65.866 89.506,70.556 v1(141.801,70.556)
  Bottom Layer w0.15: J9A.8@101.1,126.81 J9.15@101.1,131.89 ; v1(141.801,70.556) 141.801,70.678 142.05,70.927 RA36.8@142.05,72.95
NetJ10_1: J10.1 J10A.1 RA15.4 | length 145.7
  Top Layer w0.15: v1(151.007,70.952) 151.574,71.519 RA15.4@151.574,72.75
  INT2_SIG w0.15: J10A.1@65.38,114.74 69.35,114.74 82.71,128.1 112.91,128.1 133.603,107.408 135.145,107.408 136.057,106.495 143.723,106.495 144.9,105.318 144.9,99.425 143,97.525 143,83.8 143.3,83.5 143.3,71.803 146.054,69.05 149.105,69.05 v1(151.007,70.952)
  Bottom Layer w0.15: J10.1@60.3,114.74 J10A.1@65.38,114.74
NetJ10_3: J10.3 J10A.2 RA15.3 | length 143.6
  Top Layer w0.15: v1(150.477,71.482) 150.477,71.604 150.774,71.901 RA15.3@150.774,72.75
  INT2_SIG w0.15: J10A.2@65.38,117.28 71.037,117.28 82.271,128.514 113.095,128.514 133.838,107.771 135.448,107.771 136.313,106.906 143.867,106.906 145.283,105.491 145.283,99.057 144.255,98.03 144.255,82.35 143.78,81.875 143.78,71.91 146.22,69.469 148.897,69.469 149.9,70.473 149.9,70.905 v1(150.477,71.482)
  Bottom Layer w0.15: J10.3@60.3,117.28 J10A.2@65.38,117.28
NetJ11_1: J11.1 J11A.1 RA45.5 | length 74.7
  Top Layer w0.15: J11A.1@121.8,126.81 J11.1@121.8,131.89
  INT2_SIG w0.15: J11A.1@121.8,126.81 127.954,120.656 127.954,114.353 134.097,108.21 135.607,108.21 136.511,107.306 144.098,107.306 145.65,105.755 145.65,88.345 144.673,87.369 144.673,83.241 145.946,81.968 145.946,80.112 146.737,79.321 146.737,75.647 v1(147.317,75.067)
  Bottom Layer w0.15: v1(147.317,75.067) 147.439,75.067 147.844,74.662 147.844,74.156 RA45.5@147.85,74.15
NetJ11_3: J11.3 J11A.2 RA45.6 | length 73.9
  Top Layer w0.15: J11A.2@124.34,126.81 J11.3@124.34,131.89
  INT2_SIG w0.15: J11A.2@124.34,126.81 128.434,122.716 128.434,114.495 134.238,108.691 135.71,108.691 136.694,107.706 144.323,107.706 146.091,105.938 146.091,88.233 145.002,87.144 145.002,83.406 146.427,81.981 146.427,80.311 147.219,79.52 147.219,76.142 v1(147.597,75.763)
  Bottom Layer w0.15: v1(147.597,75.763) 148.35,75.01 RA45.6@148.35,74.15
NetJ11_5: J11.5 J11A.3 RA45.7 | length 72.4
  Top Layer w0.15: J11A.3@126.88,126.81 J11.5@126.88,131.89
  INT2_SIG w0.15: J11A.3@126.88,126.81 128.854,124.836 128.854,114.759 134.449,109.164 135.757,109.164 136.815,108.106 144.398,108.106 146.427,106.077 146.427,84.898 145.946,84.417 145.946,82.944 146.879,82.011 146.879,80.498 147.67,79.707 147.67,76.781 v1(148.177,76.275)
  Bottom Layer w0.15: v1(148.177,76.275) 148.85,75.602 RA45.7@148.85,74.15
NetJ11_7: J11.7 J11A.4 RA45.8 | length 71.5
  Top Layer w0.15: J11A.4@129.42,126.81 J11.7@129.42,131.89
  INT2_SIG w0.15: J11A.4@129.42,126.81 129.42,114.869 134.607,109.682 135.903,109.682 137.078,108.506 144.581,108.506 146.84,106.248 146.84,84.728 146.358,84.246 146.358,83.115 147.291,82.182 147.291,80.669 148.082,79.878 148.082,77.472 v1(148.823,76.731)
  Bottom Layer w0.15: v1(148.823,76.731) 148.823,76.667 149.35,76.14 RA45.8@149.35,74.15
NetJ12_1: J12.1 J12.9 J12A.1 J12A.5 RA22.5 | length 149.7
  INT2_SIG w0.15: v1(144.19,112.689) 147.302,115.8 174.3,115.8 178.885,120.385 v1(186.476,120.385) ; J12.9@194.55,33.7 195.81,34.96 195.81,42.6 J12.1@194.55,43.86
  Bottom Layer w0.15: RA22.5@142.65,108.2 142.65,111.148 v1@144.19,112.688 ; v1(186.476,120.385) 188.136,118.725 188.136,45.195 J12A.1@189.47,43.86 J12.1@194.55,43.86 ; J12A.5@189.47,33.7 J12.9@194.55,33.7
NetJ12_3: J12.3 J12.11 J12A.2 J12A.6 RA22.6 | length 150.5
  INT2_SIG w0.15: v1(144.189,111.939) 147.252,115 176.1,115 180.92,119.82 v1(185.95,119.82) ; J12.11@194.55,31.16 193.3,32.41 193.3,40.07 J12.3@194.55,41.32
  Bottom Layer w0.15: RA22.6@143.15,108.2 143.15,110.898 v1(144.189,111.939) ; v1(185.95,119.82) 187.1,118.67 187.1,43.69 J12A.2@189.47,41.32 J12.3@194.55,41.32 ; J12A.6@189.47,31.16 J12.11@194.55,31.16
NetJ12_5: J12.5 J12.13 J12A.3 J12A.7 RA22.7 | length 151.2
  INT2_SIG w0.15: v1(144.203,111.189) 144.205,111.189 147.116,114.1 176.4,114.1 181.625,119.325 185.35,119.325 v1(185.38,119.295) ; J12A.7@189.47,28.62 190.598,29.748 190.598,37.653 J12A.3@189.47,38.78
  Bottom Layer w0.15: RA22.7@143.65,108.2 143.65,110.642 144.197,111.189 v1(144.203,111.189) ; v1(185.38,119.295) 185.385,119.295 186.2,118.48 186.2,42.05 J12A.3@189.47,38.78 J12.5@194.55,38.78 ; J12A.7@189.47,28.62 J12.13@194.55,28.62
NetJ12_7: J12.7 J12.15 J12A.4 J12A.8 RA22.8 | length 152.1
  INT2_SIG w0.15: v1(144.19,110.433) 146.957,113.2 177.225,113.2 182.825,118.8 v1(184.8,118.8) ; J12A.8@189.47,26.08 188.27,27.28 188.27,35.04 J12A.4@189.47,36.24
  Bottom Layer w0.15: RA22.8@144.15,108.2 144.17,108.22 144.17,110.413 v1(144.19,110.433) ; v1(184.8,118.8) 185.3,118.3 185.3,40.41 J12A.4@189.47,36.24 J12.7@194.55,36.24 ; J12A.8@189.47,26.08 J12.15@194.55,26.08
NetJ14_1: J14.1 J14A.1 RA32.5 | length 113.2
  Top Layer w0.15: RA32.5@131.325,72.95 131.325,64.621 136.29,59.656 136.29,49.633 137.8,48.123 137.8,26.648 137.5,26.348 v1(137.5,26.335)
  INT2_SIG w0.15: v1(137.5,26.335) 140.465,29.3 154.8,29.3 159.2,24.9 172.735,24.9 178.835,18.8 186.68,18.8 J14A.1@189.48,16
  Bottom Layer w0.15: J14A.1@189.48,16 J14.1@194.56,16
NetJ14_3: J14.3 J14A.2 RA32.6 | length 115.6
  Top Layer w0.15: RA32.6@131.825,72.95 131.825,65.222 137.025,60.022 137.025,50.126 138.4,48.751 138.4,26.2 v1(137.5,25.3)
  INT2_SIG w0.15: v1(137.5,25.3) 141,28.8 154.472,28.8 158.997,24.275 171.982,24.275 178.034,18.223 184.717,18.223 J14A.2@189.48,13.46
  Bottom Layer w0.15: J14A.2@189.48,13.46 J14.3@194.56,13.46
NetJ14_5: J14.5 J14A.3 RA32.7 | length 116.6
  Top Layer w0.15: RA32.7@132.325,72.95 132.325,65.925 137.65,60.6 137.65,51.023 139.002,49.671 139.002,25.823 138.294,25.115 v1(138.294,25.025)
  INT2_SIG w0.15: v1(138.294,25.025) 141.569,28.3 152.243,28.3 152.825,27.718 153.982,27.718 154.86,27.718 155.249,27.329 155.249,27.015 158.3,23.963 158.3,22.929 159.372,21.857 168.577,21.857 173.034,17.4 183,17.4 J14A.3@189.48,10.92
  Bottom Layer w0.15: J14A.3@189.48,10.92 J14.5@194.56,10.92
NetJ14_7: J14.7 J14A.4 RA32.8 | length 116.3
  Top Layer w0.15: RA32.8@132.825,72.95 132.825,66.717 138.474,61.068 138.474,51.826 139.527,50.773 139.527,25.009 v1(139.108,24.589)
  INT2_SIG w0.15: v1(139.108,24.589) 141.936,27.418 152.701,27.418 153.045,27.418 153.18,27.418 154.03,26.568 157.807,22.791 157.807,21.964 158.596,21.175 168.675,21.175 173.05,16.8 181.06,16.8 J14A.4@189.48,8.38
  Bottom Layer w0.15: J14A.4@189.48,8.38 J14.7@194.56,8.38
NetJ14_9: J14.9 J14A.5 RA35.3 | length 118.3
  Top Layer w0.15: v1(133.447,51.024) 137.3,47.171 137.3,30.313 137.025,30.038 v1(137.025,30)
  INT2_SIG w0.15: v1(137.025,30) 157.8,30 158.6,30.8 164.725,30.8 169.8,25.725 173.325,25.725 175.975,23.075 184.955,23.075 191.3,16.73 191.3,7.66 J14A.5@189.48,5.84
  Bottom Layer w0.15: v1(133.447,51.024) RA35.3@133.447,69.469 ; J14A.5@189.48,5.84 J14.9@194.56,5.84
NetJ18_1: J18.1 R407.1 U45.4 U76.3 | length 22.9
  Top Layer w0.15: U76.3@178.6,176.783 178.6,176.057 178.625,176.032 178.625,174.414 178.605,174.394 J18.1@178.605,172.1 180.03,170.675 185.405,170.675 186.8,172.07 186.8,177.181 185.781,178.2 U45.4@185.05,178.2 R407.1@185.05,179.781
NetJ18_2: J18.2 R344.2 U76.4 | length 8
  Top Layer w0.15: U76.4@179.1,176.783 179.1,174.145 J18.2@181.145,172.1 R344.2@183.575,172.1
NetJ21_2: J21.2 U2.4 | length 18.3
  Top Layer w0.15: U2.4@5.977,156.438 5.977,155.874 6.107,155.745 6.782,155.745 7.154,156.116 v1(7.154,156.209)
  INT2_SIG w0.15: v1(7.154,156.209) 9.144,158.2 17.8,158.2 18.475,157.525 J21.2@22.26,157.525
NetJ23_A4/B9: J23.A4/B9 J23.B4/A9 L13.1 U12.5 | length 6.4
  Top Layer w0.3: v1(43.711,188.988) 43.716,188.983 43.716,188.044 U12.5@43.725,188.035
  Top Layer w0.4: v1(41.151,190.464) 41.1,190.515 v1(41.1,191.2) 41.3,191.4 41.3,192.573 J23.B4/A9@41.35,192.623 ; v1(46.1,190.545) v1(46.1,191.2) 46.1,192.573 J23.A4/B9@46.15,192.623
  Top Layer w0.5: L13.1@46.541,188.992 v1(46.541,190.017)
NetJ23_A5: J23.A5 R81.1 | length 20.7
  Top Layer w0.15: R81.1@40.55,187.075 v1(40.55,188.07) ; J23.A5@45,192.623 45,193.679 46.007,194.685 v1(49.15,194.685)
  Bottom Layer w0.15: v1(40.55,188.07) 41.118,187.502 45.769,187.502 49.15,190.884 v1(49.15,194.685)
NetJ23_B5: J23.B5 R80.1 | length 9.3
  Top Layer w0.15: R80.1@38.813,187.07 v1(38.813,188.065) ; J23.B5@42,192.623 42.015,192.638 v1(42.015,193.807)
  Bottom Layer w0.15: v1(38.813,188.065) 38.813,190.574 39.725,191.486 39.725,191.494 40.033,191.801 40.041,191.801 42.015,193.776 v1(42.015,193.807)
NetJ27_13: J27.13 R115.1 | length 13.9
  Top Layer w0.18: R115.1@201.6,183.317 201.6,186.742 203.65,188.792 208.6,188.792 209.25,188.143 J27.13@209.25,186.427
NetJ27_14: J27.14 R256.1 | length 15.3
  Top Layer w0.18: R256.1@200.625,183.317 200.625,186.234 203.513,189.122 208.737,189.122 209.75,188.109 J27.14@209.75,186.427
NetJ27_19: J27.19 R438.2 | length 7.6
  Top Layer w0.15: J27.19@212.25,186.427 212.25,187.767 212.425,187.942 213.179,187.942 216.325,184.797 R438.2@216.325,183.967
NetJ29_2: J29.2 R205.2 | length 3.4
  Top Layer w0.15: R205.2@10.636,15.838 10.641,15.833 J29.2@13.995,15.833
NetJ34_12: J34.12 R146.2 | length 23.1
  Top Layer w0.15: R146.2@56.105,182.255 56.105,182.305 55.68,182.73 55.63,182.73 54.907,183.453 54.907,185.543 53.821,186.629 53.821,189.451 62.845,198.475 J34.12@65.04,198.475
NetJ34_14: J34.14 R147.2 | length 18.8
  Top Layer w0.15: J34.14@54.32,198.475 51.196,195.351 51.196,188.224 54.4,185.02 R147.2@54.4,182.257
NetJ36_12: J36.12 R177.2 | length 24.6
  Bottom Layer w0.15: R177.2@73.821,186.362 73.821,188.193 71.845,190.169 71.845,192.94 75.92,197.015 81.465,197.015 82.925,198.475 J36.12@86.79,198.475
NetJ36_14: J36.14 R178.2 | length 14.4
  Bottom Layer w0.15: R178.2@72.345,186.362 72.345,188.606 71.4,189.551 71.4,193.805 J36.14@76.07,198.475
NetJ37_1: J37.1 J39.40 | length 16.9
  Top Layer w0.15: J39.40@145.55,14.775 146.5,14.775 v1(146.9,15.175)
  Bottom Layer w0.15: v1(146.9,15.175) 148.791,15.175 149.446,15.829 153.325,15.829 157.546,20.05 J37.1@160.25,20.05
NetJ37_2: J37.2 J39.42 | length 19.8
  Top Layer w0.15: J39.42@145.55,14.275 147.071,14.275 v1(147.388,14.592)
  Bottom Layer w0.15: v1(147.388,14.592) 150.374,14.592 150.541,14.425 152.505,14.425 156.968,18.888 161.628,18.888 J37.2@162.79,20.05
NetJ37_3: J37.3 J39.25 | length 13.9
  Top Layer w0.15: J39.25@153.1,18.525 154.1,18.525 154.402,18.223 v1(154.48,18.223)
  Bottom Layer w0.15: v1(154.48,18.223) 157.282,21.025 164.355,21.025 J37.3@165.33,20.05
NetJ37_4: J37.4 J39.44 | length 24.9
  Top Layer w0.15: J39.44@145.55,13.775 147.514,13.775 147.776,14.037 v1(147.898,14.037)
  Bottom Layer w0.15: v1(147.898,14.037) 152.794,14.037 157.157,18.4 166.22,18.4 J37.4@167.87,20.05
NetJ38_1: J38.1 J39.46 | length 16.2
  Top Layer w0.15: J39.46@145.55,13.275 148.196,13.275 v1(148.426,13.505)
  Bottom Layer w0.15: v1(148.426,13.505) 152.888,13.505 156.383,17 J38.1@160.25,17
NetJ38_2: J38.2 J39.48 | length 19
  Top Layer w0.15: J39.48@145.55,12.775 145.56,12.785 149.03,12.785 v1(149.04,12.795)
  Bottom Layer w0.15: v1(149.04,12.795) 152.723,12.795 155.428,15.5 161.29,15.5 J38.2@162.79,17
NetJ38_3: J38.3 J39.26 | length 25.8
  Top Layer w0.15: J39.26@145.55,18.275 145.573,18.298 146.994,18.298 v1(147.82,19.125)
  INT2_SIG w0.15: v1(147.82,19.125) 152.777,19.125 159.021,12.881 163.533,12.881 164.15,13.498 164.15,15.82 J38.3@165.33,17
NetJ38_4: J38.4 J39.23 | length 21.3
  Top Layer w0.15: J39.23@153.1,19.025 153.115,19.04 154.334,19.04 v1(154.349,19.055)
  Bottom Layer w0.15: v1(154.349,19.055) 154.467,19.055 156.737,21.325 168.234,21.325 169.125,20.434 169.125,18.255 J38.4@167.87,17
NetJ39_1: J39.1 R188.1 U63.2 X27.1 | length 53
  Top Layer w0.15: J39.1@153.1,24.525 154.031,24.525 154.119,24.613 154.119,26.537 153.339,27.318 153.339,28.243 153.345,28.249 v1(153.345,28.254) ; v1(168.706,59.198) 168.707,59.199 169.899,59.199 X27.1@169.9,59.2
  Bottom Layer w0.15: v1(153.345,28.254) 153.339,28.254 153.339,30.851 163.384,40.896 164.65,40.896 168.707,44.953 168.707,48.299 171.187,50.78 171.187,56.717 v1(168.706,59.198) 168.656,59.148 164.35,59.148 164.1,59.398 U63.2@164.1,60.148 R188.1@164.1,61.321
NetJ39_6: J39.6 J41.1 R196.1 | length 20.8
  Top Layer w0.15: J39.6@145.55,23.275 147.247,23.275 v1(147.687,22.835) ; R196.1@160.25,12.125 J41.1@160.25,14.125
  INT2_SIG w0.15: v1(147.687,22.835) 148.254,22.835 149.839,21.25 151.183,21.25 151.558,20.875 152.242,20.875 152.617,21.25 153.125,21.25 J41.1@160.25,14.125
NetJ39_8: J39.8 J41.2 R195.2 | length 24.8
  Top Layer w0.15: J39.8@145.55,22.775 146.471,22.775 v1(147.071,22.175) ; R195.2@162.79,12.125 J41.2@162.79,14.125
  INT2_SIG w0.15: v1(147.071,22.175) 147.071,23.17 147.326,23.425 148.109,23.425 148.171,23.363 149.923,21.611 151.068,21.611 151.095,21.638 151.22,21.638 151.683,21.175 152.117,21.175 152.553,21.611 153.189,21.611 159.624,15.175 161.74,15.175 J41.2@162.79,14.125
NetJ39_21: J39.21 Q6.1 R186.1 X60.1 | length 61.3
  Top Layer w0.15: J39.21@153.1,19.525 153.107,19.532 154.012,19.532 155.12,20.64 155.12,26.278 154.424,26.975 v1(154.424,27.093) ; v1(160.453,56.459) 161.002,57.008 v1(168.706,57.008) X60.1@169.875,57.008
  Bottom Layer w0.15: v1(154.424,27.093) 154.365,27.034 153.869,27.53 153.309,27.53 152.814,28.026 152.814,30.75 161.886,39.823 161.886,42.365 161.922,42.4 161.922,42.671 170.826,51.575 170.887,51.575 170.887,55.687 169.566,57.008 v1(168.706,57.008) ; Q6.1@159.839,57.748 159.839,57.073 v1(160.453,56.459) R186.1@161.364,56.459
NetJ39_38: J39.38 R185.1 | length 2
  Top Layer w0.15: R185.1@143.558,15.275 J39.38@145.55,15.275
NetJ39_50: J39.50 R183.2 X61.1 | length 218.7
  Top Layer w0.15: v1(143.161,14.275) 143.183,14.275 143.558,13.9 143.558,13.367 144.638,12.287 145.538,12.287 J39.50@145.55,12.275 ; R183.2@213.35,127.1 X61.1@213.35,129.025 ; R183.2@213.4,127.1 214.625,128.325 217.555,128.325 v1(219.5,126.38)
  INT2_SIG w0.15: v1(143.161,14.275) 142.648,14.788 142.648,20.701 143.972,22.025 146.259,22.025 147.042,21.242 147.042,18.888 153.223,12.706 157.089,12.706 157.59,12.205 162.675,12.205 167.905,6.975 185.26,6.975 187.835,4.4 203.869,4.4 213.3,13.831 213.3,57.934 218.9,63.534 218.9,95.387 219.1,95.587 219.1,109.5 219.825,110.225 219.825,113.794 219.436,114.183 219.436,126.316 v1(219.5,126.38)
NetJ39_66: J39.66 R191.2 | length 8.1
  Top Layer w0.15: v1(142.791,13.375) 142.791,9.938 144.453,8.275 J39.66@145.55,8.275
  Bottom Layer w0.15: R191.2@141.559,13.375 v1(142.791,13.375)
NetJ39_67: J39.67 J41.3 R193.2 | length 19.6
  Top Layer w0.15: J39.67@153.1,8.025 154.027,8.025 154.25,8.248 154.25,9.608 155.317,10.675 156.106,10.675 158.45,13.019 158.45,14.591 159.359,15.5 163.955,15.5 J41.3@165.33,14.125 R193.2@165.33,12.125
NetJ43_38: J43.38 R203.1 X70.1 | length 20.9
  Top Layer w0.15: J43.38@156.05,100.8 157.375,100.8 158.1,100.075 158.1,98.774 161.25,95.624 161.741,95.624 162.1,95.265 164.815,95.265 168.425,98.875 R203.1@168.425,101.321 X70.1@166.85,101.321
NetJ43_40: J43.40 J62.1 | length 26
  Top Layer w0.15: J43.40@156.05,100.3 157.075,100.3 157.725,99.65 157.725,98.725 161.126,95.324 161.505,95.324 161.994,94.835 164.935,94.835 168.75,98.65 169.791,98.65 172.52,101.379 172.52,102.92 173.271,103.671 173.271,104.165 J62.1@173.946,104.84
NetJ43_42: J43.42 J62.2 | length 23.9
  Top Layer w0.15: J43.42@156.05,99.8 156.968,99.8 157.425,99.343 157.425,98.475 160.876,95.024 161.38,95.024 161.869,94.535 165.159,94.535 168.899,98.275 170.103,98.275 173.946,102.119 J62.2@173.946,102.3
NetJ43_44: J43.44 J62.3 | length 22.8
  Top Layer w0.15: J43.44@156.05,99.3 156.97,99.3 157.125,99.145 157.125,98.275 160.676,94.724 161.256,94.724 161.745,94.235 165.433,94.235 169.099,97.9 170.382,97.9 172.242,99.76 J62.3@173.946,99.76
NetJ43_50: J43.50 R199.2 X67.1 | length 26.8
  Top Layer w0.15: J43.50@156.05,97.8 157.1,97.8 158.475,96.425 158.475,93.8 160.2,92.075 160.2,90.494 161.094,89.6 165.431,89.6 166.85,91.019 166.85,95.15 168.6,96.9 X67.1@169.921,96.9 R199.2@171.546,96.9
